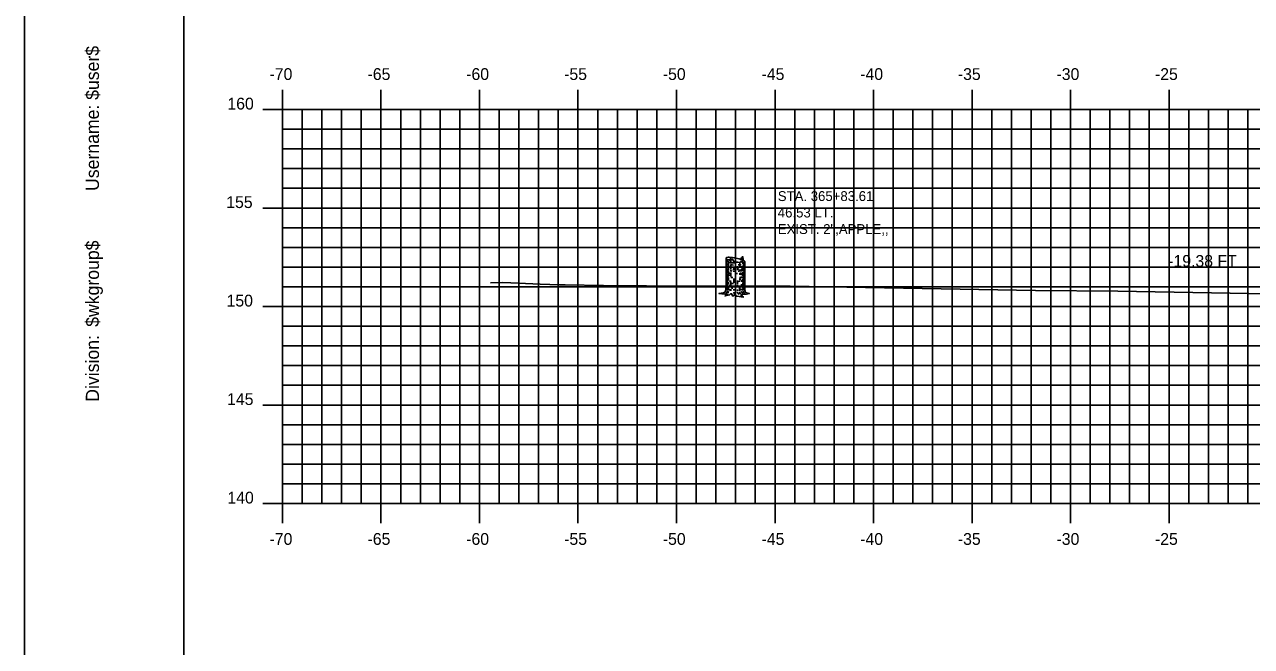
# Model space of a CAD drawing. Extents: x 1147412 to 1147582, y 608981 to 609091.
# Drawn here: x 1147411.6 to 1147473.9, y 609013.1 to 609044.6 of the extents above; entities that cross this region are included whole.
import ezdxf

# ---------------------------------------------------------------- set-up
doc = ezdxf.new("R2010")
doc.units = 0
for name, color, linetype in [('BORDER', 7, 'Continuous'), ('D_Text_Monospaced', 7, 'Continuous'), ('D_Text_Standard', 7, 'Continuous'), ('H_V ANNOTATION', 7, 'Continuous'), ('MAJOR', 7, 'Continuous'), ('MINOR', 7, 'Continuous'), ('PLOT BOUNDARY', 7, 'Continuous'), ('S_Roadway_Centerline', 7, 'Continuous'), ('S_Trees_Decid_NonPay', 7, 'Continuous')]:
    doc.layers.add(name, color=color, linetype=linetype)

msp = doc.modelspace()

# ---------------------------------------------------------------- linework, layer by layer
at = {"layer": 'BORDER'}
msp.add_lwpolyline([(1147419.698, 608984.335), (1147579.698, 608984.335), (1147579.698, 609089.335), (1147419.698, 609089.335)], close=True, dxfattribs=at)
at = {"layer": 'MAJOR'}
for p, q in [((1147424.697, 609041.337), (1147424.697, 609040.335)), ((1147429.697, 609041.337), (1147429.697, 609040.335)), ((1147434.697, 609041.337), (1147434.697, 609040.335)), ((1147439.697, 609041.337), (1147439.697, 609040.335)), ((1147444.697, 609041.337), (1147444.697, 609040.335)), ((1147449.697, 609041.337), (1147449.697, 609040.335)), ((1147454.697, 609041.337), (1147454.697, 609040.335)), ((1147459.697, 609041.337), (1147459.697, 609040.335)), ((1147464.697, 609041.337), (1147464.697, 609040.335)), ((1147469.697, 609041.337), (1147469.697, 609040.335)), ((1147423.695, 609040.335), (1147424.697, 609040.335)), ((1147424.697, 609040.335), (1147564.697, 609040.335)), ((1147424.697, 609020.335), (1147424.697, 609040.335)), ((1147424.697, 609020.335), (1147424.697, 609040.335)), ((1147424.697, 609040.335), (1147564.697, 609040.335)), ((1147429.697, 609020.335), (1147429.697, 609040.335)), ((1147434.697, 609020.335), (1147434.697, 609040.335)), ((1147439.697, 609020.335), (1147439.697, 609040.335)), ((1147444.697, 609020.335), (1147444.697, 609040.335)), ((1147449.697, 609020.335), (1147449.697, 609040.335)), ((1147454.697, 609020.335), (1147454.697, 609040.335)), ((1147459.697, 609020.335), (1147459.697, 609040.335)), ((1147464.697, 609020.335), (1147464.697, 609040.335)), ((1147469.697, 609020.335), (1147469.697, 609040.335)), ((1147423.695, 609035.335), (1147424.697, 609035.335)), ((1147424.697, 609035.335), (1147564.697, 609035.335)), ((1147423.695, 609030.335), (1147424.697, 609030.335)), ((1147424.697, 609030.335), (1147564.697, 609030.335)), ((1147423.695, 609025.335), (1147424.697, 609025.335)), ((1147424.697, 609025.335), (1147564.697, 609025.335)), ((1147423.695, 609020.335), (1147424.697, 609020.335)), ((1147424.697, 609020.335), (1147564.697, 609020.335)), ((1147424.697, 609020.335), (1147564.697, 609020.335)), ((1147424.697, 609019.333), (1147424.697, 609020.335)), ((1147429.697, 609019.333), (1147429.697, 609020.335)), ((1147434.697, 609019.333), (1147434.697, 609020.335)), ((1147439.697, 609019.333), (1147439.697, 609020.335)), ((1147444.697, 609019.333), (1147444.697, 609020.335)), ((1147449.697, 609019.333), (1147449.697, 609020.335)), ((1147454.697, 609019.333), (1147454.697, 609020.335)), ((1147459.697, 609019.333), (1147459.697, 609020.335)), ((1147464.697, 609019.333), (1147464.697, 609020.335)), ((1147469.697, 609019.333), (1147469.697, 609020.335))]:
    msp.add_line(p, q, dxfattribs=at)
at = {"layer": 'MINOR'}
for p, q in [((1147425.697, 609020.335), (1147425.697, 609040.335)), ((1147426.697, 609020.335), (1147426.697, 609040.335)), ((1147427.697, 609020.335), (1147427.697, 609040.335)), ((1147428.697, 609020.335), (1147428.697, 609040.335)), ((1147430.697, 609020.335), (1147430.697, 609040.335)), ((1147431.697, 609020.335), (1147431.697, 609040.335)), ((1147432.697, 609020.335), (1147432.697, 609040.335)), ((1147433.697, 609020.335), (1147433.697, 609040.335)), ((1147435.697, 609020.335), (1147435.697, 609040.335)), ((1147436.697, 609020.335), (1147436.697, 609040.335)), ((1147437.697, 609020.335), (1147437.697, 609040.335)), ((1147438.697, 609020.335), (1147438.697, 609040.335)), ((1147440.697, 609020.335), (1147440.697, 609040.335)), ((1147441.697, 609020.335), (1147441.697, 609040.335)), ((1147442.697, 609020.335), (1147442.697, 609040.335)), ((1147443.697, 609020.335), (1147443.697, 609040.335)), ((1147445.697, 609020.335), (1147445.697, 609040.335)), ((1147446.697, 609020.335), (1147446.697, 609040.335)), ((1147447.697, 609020.335), (1147447.697, 609040.335)), ((1147448.697, 609020.335), (1147448.697, 609040.335)), ((1147450.697, 609020.335), (1147450.697, 609040.335)), ((1147451.697, 609020.335), (1147451.697, 609040.335)), ((1147452.697, 609020.335), (1147452.697, 609040.335)), ((1147453.697, 609020.335), (1147453.697, 609040.335)), ((1147455.697, 609020.335), (1147455.697, 609040.335)), ((1147456.697, 609020.335), (1147456.697, 609040.335)), ((1147457.697, 609020.335), (1147457.697, 609040.335)), ((1147458.697, 609020.335), (1147458.697, 609040.335)), ((1147460.697, 609020.335), (1147460.697, 609040.335)), ((1147461.697, 609020.335), (1147461.697, 609040.335)), ((1147462.697, 609020.335), (1147462.697, 609040.335)), ((1147463.697, 609020.335), (1147463.697, 609040.335)), ((1147465.697, 609020.335), (1147465.697, 609040.335)), ((1147466.697, 609020.335), (1147466.697, 609040.335)), ((1147467.697, 609020.335), (1147467.697, 609040.335)), ((1147468.697, 609020.335), (1147468.697, 609040.335)), ((1147470.697, 609020.335), (1147470.697, 609040.335)), ((1147471.697, 609020.335), (1147471.697, 609040.335)), ((1147472.697, 609020.335), (1147472.697, 609040.335)), ((1147473.697, 609020.335), (1147473.697, 609040.335)), ((1147424.697, 609039.335), (1147564.697, 609039.335)), ((1147424.697, 609039.335), (1147425.699, 609039.335)), ((1147424.697, 609038.335), (1147564.697, 609038.335)), ((1147424.697, 609038.335), (1147425.699, 609038.335)), ((1147424.697, 609037.335), (1147564.697, 609037.335)), ((1147424.697, 609037.335), (1147425.699, 609037.335)), ((1147424.697, 609036.335), (1147564.697, 609036.335)), ((1147424.697, 609036.335), (1147425.699, 609036.335)), ((1147424.697, 609034.335), (1147564.697, 609034.335)), ((1147424.697, 609034.335), (1147425.699, 609034.335)), ((1147424.697, 609033.335), (1147564.697, 609033.335)), ((1147424.697, 609033.335), (1147425.699, 609033.335)), ((1147424.697, 609032.335), (1147564.697, 609032.335)), ((1147424.697, 609032.335), (1147425.699, 609032.335)), ((1147424.697, 609031.335), (1147564.697, 609031.335)), ((1147424.697, 609031.335), (1147425.699, 609031.335)), ((1147424.697, 609029.335), (1147564.697, 609029.335)), ((1147424.697, 609029.335), (1147425.699, 609029.335)), ((1147424.697, 609028.335), (1147564.697, 609028.335)), ((1147424.697, 609028.335), (1147425.699, 609028.335)), ((1147424.697, 609027.335), (1147564.697, 609027.335)), ((1147424.697, 609027.335), (1147425.699, 609027.335)), ((1147424.697, 609026.335), (1147564.697, 609026.335)), ((1147424.697, 609026.335), (1147425.699, 609026.335)), ((1147424.697, 609024.335), (1147564.697, 609024.335)), ((1147424.697, 609024.335), (1147425.699, 609024.335)), ((1147424.697, 609023.335), (1147564.697, 609023.335)), ((1147424.697, 609023.335), (1147425.699, 609023.335)), ((1147424.697, 609022.335), (1147564.697, 609022.335)), ((1147424.697, 609022.335), (1147425.699, 609022.335)), ((1147424.697, 609021.335), (1147564.697, 609021.335)), ((1147424.697, 609021.335), (1147425.699, 609021.335))]:
    msp.add_line(p, q, dxfattribs=at)
at = {"layer": 'PLOT BOUNDARY'}
msp.add_lwpolyline([(1147411.604, 608981.276), (1147581.604, 608981.276), (1147581.604, 609091.276), (1147411.604, 609091.276)], close=True, dxfattribs=at)
at = {"layer": 'S_Roadway_Centerline'}
msp.add_lwpolyline([(1147435.257, 609031.545), (1147435.842, 609031.546), (1147436.283, 609031.53), (1147437.773, 609031.477), (1147438.759, 609031.444), (1147439.053, 609031.435), (1147440.99, 609031.398), (1147443.169, 609031.384), (1147450.474, 609031.373), (1147462.918, 609031.149), (1147467.093, 609031.118), (1147476.613, 609030.948)], dxfattribs=at)
at = {"layer": 'S_Trees_Decid_NonPay'}
for p, q in [((1147447.272, 609032.74), (1147447.272, 609032.645)), ((1147447.272, 609032.419), (1147447.272, 609032.336)), ((1147447.272, 609032.267), (1147447.272, 609032.015)), ((1147447.341, 609032.653), (1147447.341, 609032.353)), ((1147447.341, 609032.324), (1147447.341, 609032.192)), ((1147447.341, 609032.158), (1147447.341, 609031.878)), ((1147447.459, 609032.67), (1147447.459, 609032.522)), ((1147447.459, 609032.474), (1147447.459, 609032.305)), ((1147447.606, 609032.624), (1147447.606, 609032.517)), ((1147447.606, 609032.289), (1147447.606, 609032.202)), ((1147447.606, 609032.168), (1147447.606, 609032.097)), ((1147447.786, 609032.388), (1147447.786, 609032.188)), ((1147447.904, 609032.572), (1147447.904, 609032.493)), ((1147447.904, 609032.406), (1147447.904, 609032.322)), ((1147447.904, 609032.211), (1147447.904, 609032.11)), ((1147447.99, 609032.388), (1147447.99, 609032.301)), ((1147447.99, 609032.231), (1147447.99, 609032.11)), ((1147448.061, 609032.561), (1147448.061, 609032.509)), ((1147448.061, 609032.406), (1147448.061, 609032.324)), ((1147448.061, 609032.289), (1147448.061, 609032.215)), ((1147448.061, 609032.188), (1147448.061, 609032.128)), ((1147448.104, 609032.566), (1147448.104, 609032.349)), ((1147448.104, 609032.28), (1147448.104, 609032.128)), ((1147448.131, 609032.496), (1147448.131, 609032.414)), ((1147448.131, 609032.345), (1147448.131, 609032.215)), ((1147448.131, 609032.192), (1147448.131, 609032.011)), ((1147447.272, 609031.933), (1147447.272, 609031.702)), ((1147447.272, 609031.632), (1147447.272, 609031.471)), ((1147447.341, 609031.807), (1147447.341, 609031.663)), ((1147447.341, 609031.593), (1147447.341, 609031.451)), ((1147447.459, 609031.999), (1147447.459, 609031.851)), ((1147447.459, 609031.581), (1147447.459, 609031.428)), ((1147447.606, 609031.764), (1147447.606, 609031.542)), ((1147447.786, 609031.65), (1147447.786, 609031.463)), ((1147447.904, 609032.025), (1147447.904, 609031.949)), ((1147447.904, 609031.764), (1147447.904, 609031.667)), ((1147447.99, 609032.034), (1147447.99, 609031.92)), ((1147447.99, 609031.858), (1147447.99, 609031.776)), ((1147447.99, 609031.69), (1147447.99, 609031.593)), ((1147448.061, 609032.075), (1147448.061, 609031.894)), ((1147448.061, 609031.862), (1147448.061, 609031.78)), ((1147448.061, 609031.727), (1147448.061, 609031.556)), ((1147448.061, 609031.523), (1147448.061, 609031.243)), ((1147448.104, 609032.023), (1147448.104, 609031.945)), ((1147448.104, 609031.918), (1147448.104, 609031.811)), ((1147448.104, 609031.776), (1147448.104, 609031.675)), ((1147448.104, 609031.65), (1147448.104, 609031.467)), ((1147448.131, 609031.963), (1147448.131, 609031.717)), ((1147448.131, 609031.698), (1147448.131, 609031.603)), ((1147448.133, 609031.55), (1147448.131, 609031.29)), ((1147447.272, 609031.455), (1147447.272, 609031.35)), ((1147447.272, 609031.313), (1147447.272, 609031.189)), ((1147447.34, 609031.109), (1147447.299, 609031.013)), ((1147447.341, 609031.35), (1147447.341, 609031.169)), ((1147447.459, 609031.216), (1147447.459, 609031.138)), ((1147447.606, 609031.208), (1147447.606, 609031.142)), ((1147447.646, 609030.922), (1147447.612, 609031.068)), ((1147447.786, 609031.433), (1147447.786, 609031.379)), ((1147447.786, 609031.204), (1147447.786, 609031.113)), ((1147447.904, 609031.342), (1147447.904, 609031.118)), ((1147447.99, 609031.463), (1147447.99, 609031.364)), ((1147447.99, 609031.235), (1147447.99, 609031.177)), ((1147448.061, 609031.191), (1147448.061, 609031.165)), ((1147448.102, 609031.126), (1147448.137, 609031.074)), ((1147448.104, 609031.364), (1147448.104, 609031.173)), ((1147448.184, 609031.004), (1147448.116, 609031.035)), ((1147448.131, 609031.252), (1147448.131, 609031.177))]:
    msp.add_line(p, q, dxfattribs=at)
for points in [[(1147448.172, 609032.604), (1147448.172, 609031.192), (1147448.194, 609031.044), (1147448.398, 609031), (1147448.258, 609030.965), (1147448.04, 609030.946), (1147447.97, 609030.903), (1147448.091, 609030.815), (1147447.76, 609030.858), (1147447.646, 609030.922), (1147447.554, 609030.862), (1147447.498, 609030.941), (1147447.507, 609030.977), (1147447.445, 609030.979), (1147447.393, 609030.922), (1147447.161, 609030.87), (1147447.288, 609030.959), (1147447.156, 609030.961), (1147446.848, 609030.998), (1147447.087, 609031.029), (1147447.165, 609031.087), (1147447.204, 609031.208), (1147447.221, 609031.562), (1147447.221, 609032.795)], [(1147447.585, 609032.629), (1147447.576, 609032.696), (1147447.552, 609032.701), (1147447.543, 609032.736), (1147447.513, 609032.721), (1147447.498, 609032.736), (1147447.474, 609032.713), (1147447.451, 609032.721), (1147447.438, 609032.771), (1147447.431, 609032.727), (1147447.4, 609032.736), (1147447.396, 609032.685)], [(1147448.077, 609032.685), (1147448.073, 609032.779), (1147448.059, 609032.752), (1147448.059, 609032.874), (1147448.038, 609032.81), (1147448.023, 609032.843), (1147448.007, 609032.787), (1147447.99, 609032.804), (1147447.972, 609032.795), (1147447.953, 609032.729)], [(1147448.055, 609032.561), (1147448.038, 609032.622), (1147448.015, 609032.61), (1147447.984, 609032.645), (1147447.951, 609032.567)], [(1147447.27, 609031.147), (1147447.261, 609031.07), (1147447.183, 609031.021)], [(1147447.795, 609031.064), (1147447.795, 609031.027), (1147447.846, 609030.996), (1147447.863, 609030.946)], [(1147447.906, 609031.07), (1147447.912, 609031), (1147447.976, 609030.988)], [(1147448.054, 609031.035), (1147448.011, 609031.07), (1147448.003, 609031.118)], [(1147448.133, 609031.051), (1147448.054, 609031.035), (1147448.038, 609030.992)]]:
    msp.add_lwpolyline(points, dxfattribs=at)
for centre, radius, start, end in [((1147447.239, 609032.796), 0.0179, 152.11676, 168.17229), ((1147447.239, 609032.796), 0.0179, 168.17229, 184.22782), ((1147447.245, 609032.796), 0.0237, 184.22782, 198.17229), ((1147447.254, 609032.799), 0.0336, 198.17229, 216.94859), ((1147447.244, 609032.793), 0.0237, 138.17229, 152.11676), ((1147447.251, 609032.786), 0.0336, 119.39599, 138.17229), ((1147447.302, 609032.835), 0.0935, 216.9486, 228.17229), ((1147447.281, 609032.734), 0.0935, 108.17229, 119.39599), ((1147447.454, 609033.005), 0.322, 228.17229, 250.29024), ((1147447.352, 609032.517), 0.322, 86.05435, 108.17229), ((1147447.202, 609030.337), 2.507, 78.17229, 86.05435), ((1147447.202, 609030.337), 2.507, 70.29024, 78.17229), ((1147447.239, 609032.648), 0.0191, 163.94846, 180), ((1147447.239, 609032.648), 0.0191, 180, 196.05154), ((1147447.239, 609032.434), 0.0191, 163.94846, 180), ((1147447.239, 609032.434), 0.0191, 180, 196.05154), ((1147447.239, 609032.331), 0.0191, 163.94846, 180), ((1147447.239, 609032.331), 0.0191, 180, 196.05154), ((1147447.239, 609032.111), 0.0191, 163.94846, 180), ((1147447.239, 609032.111), 0.0191, 180, 196.05154), ((1147447.245, 609032.65), 0.0252, 196.05154, 210), ((1147447.245, 609032.436), 0.0252, 196.05154, 210), ((1147447.245, 609032.333), 0.0252, 196.05154, 210), ((1147447.245, 609032.113), 0.0252, 196.05154, 210), ((1147447.254, 609032.655), 0.0356, 210, 228.74941), ((1147447.254, 609032.441), 0.0356, 210, 228.74941), ((1147447.254, 609032.338), 0.0356, 210, 228.74941), ((1147447.296, 609032.702), 0.0984, 228.74941, 240), ((1147447.296, 609032.488), 0.0984, 228.74941, 240), ((1147447.296, 609032.385), 0.0984, 228.74941, 240), ((1147447.409, 609032.899), 0.326, 240, 248.32432), ((1147447.409, 609032.685), 0.326, 240, 243.57187), ((1147447.409, 609032.582), 0.326, 240, 243.24303), ((1147447.409, 609032.786), 0.326, 240.90989, 257.8036), ((1147447.409, 609032.477), 0.326, 245.15448, 257.8036), ((1147447.409, 609032.685), 0.326, 250.41675, 261.8968), ((1147447.409, 609032.582), 0.326, 251.68306, 257.8036), ((1147447.409, 609032.899), 0.326, 257.8036, 261.8968), ((1147448.191, 609035.062), 2.507, 250.29024, 251.52809), ((1147447.696, 609034.909), 2.356, 261.8968, 263.27991), ((1147447.696, 609034.695), 2.356, 261.8968, 262.55191), ((1147447.696, 609034.487), 2.356, 263.26817, 265.63617), ((1147447.696, 609034.592), 2.356, 263.34129, 264.99462), ((1147447.696, 609034.796), 2.356, 264.24201, 267.36728), ((1147447.696, 609034.909), 2.356, 265.24001, 267.83857), ((1147447.696, 609034.592), 2.356, 266.50356, 267.83857), ((1147448.191, 609035.062), 2.507, 255.99867, 258.17229), ((1147448.191, 609035.062), 2.507, 258.17229, 264.50134), ((1147447.696, 609034.695), 2.356, 270.81188, 272.1981), ((1147447.696, 609034.592), 2.356, 272.1981, 273.97408), ((1147447.696, 609034.487), 2.356, 273.0067, 275.06467), ((1147447.696, 609034.796), 2.356, 273.14807, 276.77338), ((1147447.696, 609034.695), 2.356, 275.06468, 278.1032), ((1147447.696, 609034.487), 2.356, 277.18685, 278.1032), ((1147447.696, 609034.592), 2.356, 277.38384, 278.1032), ((1147447.982, 609032.685), 0.326, 278.1032, 279.08543), ((1147447.982, 609032.582), 0.326, 278.1032, 284.03823), ((1147447.982, 609032.477), 0.326, 278.1032, 284.03823), ((1147447.939, 609032.394), 0.322, 48.17229, 70.29024), ((1147448.041, 609032.882), 0.322, 272.44787, 288.17229), ((1147447.982, 609032.786), 0.326, 291.95057, 300), ((1147447.982, 609032.685), 0.326, 291.95057, 300), ((1147447.982, 609032.477), 0.326, 291.95057, 300), ((1147448.112, 609032.665), 0.0935, 288.17229, 299.39599), ((1147448.096, 609032.589), 0.0984, 300, 311.25059), ((1147448.096, 609032.488), 0.0984, 300, 311.25059), ((1147448.096, 609032.28), 0.0984, 300, 311.25059), ((1147448.091, 609032.564), 0.0935, 36.9486, 48.17229), ((1147448.141, 609032.613), 0.0336, 299.39599, 318.17229), ((1147448.137, 609032.542), 0.0356, 311.25059, 330), ((1147448.137, 609032.441), 0.0356, 311.25059, 330), ((1147448.137, 609032.233), 0.0356, 311.25059, 330), ((1147448.139, 609032.6), 0.0336, 18.17229, 36.94859), ((1147448.149, 609032.607), 0.0237, 318.17229, 332.11676), ((1147448.146, 609032.537), 0.0252, 330, 343.94846), ((1147448.146, 609032.436), 0.0252, 330, 343.94846), ((1147448.146, 609032.228), 0.0252, 330, 343.94846), ((1147448.146, 609032.113), 0.0252, 330, 343.94846), ((1147448.154, 609032.604), 0.0179, 332.11676, 348.17229), ((1147448.152, 609032.535), 0.0191, 343.94846, 360), ((1147448.152, 609032.434), 0.0191, 343.94846, 360), ((1147448.152, 609032.331), 0.0191, 343.94846, 360), ((1147448.152, 609032.226), 0.0191, 343.94846, 360), ((1147448.152, 609032.111), 0.0191, 343.94846, 360), ((1147448.148, 609032.604), 0.0237, 4.22782, 18.17229), ((1147448.154, 609032.604), 0.0179, 348.17229, 4.22783), ((1147448.152, 609032.535), 0.0191, 360, 6.11276), ((1147448.152, 609032.434), 0.0191, 360, 6.11276), ((1147448.152, 609032.331), 0.0191, 360, 6.11276), ((1147448.152, 609032.226), 0.0191, 360, 6.11276), ((1147448.152, 609032.111), 0.0191, 360, 6.11276), ((1147447.237, 609031.896), 0.0191, 163.94846, 180), ((1147447.239, 609031.792), 0.0191, 163.94846, 180), ((1147447.239, 609031.792), 0.0191, 180, 196.05154), ((1147447.24, 609031.997), 0.0191, 163.94846, 180), ((1147447.24, 609031.997), 0.0191, 180, 196.05154), ((1147447.245, 609031.793), 0.0252, 196.05154, 210), ((1147447.246, 609031.998), 0.0252, 196.05154, 210), ((1147447.254, 609032.118), 0.0356, 210, 228.74941), ((1147447.254, 609031.799), 0.0356, 210, 228.74941), ((1147447.255, 609032.004), 0.0356, 210, 228.74941), ((1147447.296, 609032.165), 0.0984, 228.74941, 240), ((1147447.296, 609032.051), 0.0984, 228.74941, 240), ((1147447.296, 609031.846), 0.0984, 228.74941, 240), ((1147447.407, 609032.148), 0.326, 240, 256.90786), ((1147447.409, 609032.362), 0.326, 240, 245.15448), ((1147447.409, 609032.043), 0.326, 240, 245.15448), ((1147447.41, 609032.248), 0.326, 240, 247.86558), ((1147447.409, 609031.952), 0.326, 241.93896, 253.9183), ((1147447.41, 609032.248), 0.326, 257.66994, 261.8968), ((1147447.696, 609034.258), 2.356, 261.8968, 262.86151), ((1147447.696, 609033.962), 2.356, 262.58433, 264.48651), ((1147447.696, 609034.372), 2.356, 262.65877, 264.79114), ((1147447.696, 609033.849), 2.356, 264.24201, 267.46903), ((1147447.693, 609034.158), 2.356, 264.3443, 266.85288), ((1147447.696, 609034.053), 2.356, 267.83857, 269.00542), ((1147447.696, 609034.372), 2.356, 269.55779, 270), ((1147447.696, 609034.372), 2.356, 270, 272.414), ((1147447.696, 609033.962), 2.356, 272.1981, 275.27259), ((1147447.693, 609034.158), 2.356, 274.97344, 277.24554), ((1147447.696, 609034.372), 2.356, 275.06467, 277.18685), ((1147447.696, 609034.053), 2.356, 275.06467, 276.42799), ((1147447.982, 609032.362), 0.326, 284.03823, 300), ((1147447.983, 609032.248), 0.326, 283.90364, 291.80982), ((1147447.982, 609032.043), 0.326, 284.03823, 291.95057), ((1147447.982, 609031.839), 0.326, 284.03823, 291.95057), ((1147447.979, 609032.148), 0.326, 292.40493, 300), ((1147447.983, 609032.248), 0.326, 297.00583, 300), ((1147447.982, 609032.043), 0.326, 297.15252, 300), ((1147448.093, 609031.95), 0.0984, 300, 311.25059), ((1147448.096, 609032.165), 0.0984, 300, 311.25059), ((1147448.096, 609031.846), 0.0984, 300, 311.25059), ((1147448.096, 609032.051), 0.0984, 300, 311.25059), ((1147448.135, 609031.903), 0.0356, 311.25059, 330), ((1147448.137, 609032.118), 0.0356, 311.25059, 330), ((1147448.138, 609032.004), 0.0356, 311.25059, 330), ((1147448.137, 609031.799), 0.0356, 311.25059, 330), ((1147448.144, 609031.898), 0.0252, 330, 343.94846), ((1147448.15, 609031.896), 0.0191, 343.94846, 360), ((1147448.146, 609031.793), 0.0252, 330, 343.94846), ((1147448.147, 609031.998), 0.0252, 330, 343.94846), ((1147448.15, 609031.896), 0.0191, 0, 6.11277), ((1147448.152, 609031.792), 0.0191, 343.94846, 360), ((1147448.153, 609031.997), 0.0191, 343.94846, 360), ((1147448.152, 609031.792), 0.0191, 360, 6.11276), ((1147448.152, 609031.701), 0.0191, 360, 6.11276), ((1147448.153, 609031.997), 0.0191, 0, 6.11277), ((1147447.225, 609031.252), 0.0191, 163.94846, 180), ((1147447.225, 609031.252), 0.0191, 180, 196.05154), ((1147447.231, 609031.253), 0.0252, 196.05154, 210), ((1147447.24, 609031.259), 0.0356, 210, 228.74941), ((1147447.23, 609031.362), 0.0191, 163.94846, 180), ((1147447.23, 609031.362), 0.0191, 180, 196.05154), ((1147447.236, 609031.364), 0.0252, 196.05154, 210), ((1147447.245, 609031.369), 0.0356, 210, 228.74941), ((1147447.235, 609031.473), 0.0191, 163.94846, 180), ((1147447.235, 609031.473), 0.0191, 180, 196.05154), ((1147447.281, 609031.306), 0.0984, 228.74941, 240), ((1147447.241, 609031.474), 0.0252, 196.05154, 210), ((1147447.25, 609031.479), 0.0356, 210, 228.74941), ((1147447.287, 609031.416), 0.0984, 228.74941, 240), ((1147447.291, 609031.527), 0.0984, 228.74941, 240), ((1147447.395, 609031.503), 0.326, 240, 247.9161), ((1147447.4, 609031.613), 0.326, 240, 241.90969), ((1147447.405, 609031.724), 0.326, 240, 245.93749), ((1147447.395, 609031.503), 0.326, 260.38342, 261.8968), ((1147447.681, 609033.513), 2.356, 261.8968, 263.53328), ((1147447.692, 609033.734), 2.356, 262.22258, 264.4852), ((1147447.687, 609033.623), 2.356, 264.90887, 266.81578), ((1147447.687, 609033.623), 2.356, 274.18643, 275.28293), ((1147447.681, 609033.513), 2.356, 274.55512, 275.4167), ((1147447.692, 609033.734), 2.356, 277.28629, 278.1032), ((1147447.681, 609033.513), 2.356, 277.54032, 278.1032), ((1147447.967, 609031.503), 0.326, 278.1032, 294.70938), ((1147447.978, 609031.724), 0.326, 278.1032, 284.77414), ((1147447.973, 609031.613), 0.326, 293.6544, 300), ((1147448.081, 609031.306), 0.0984, 300, 311.25059), ((1147448.092, 609031.527), 0.0984, 300, 311.25059), ((1147448.123, 609031.259), 0.0356, 311.25059, 330), ((1147448.132, 609031.253), 0.0252, 330, 343.94846), ((1147448.133, 609031.479), 0.0356, 311.25059, 330), ((1147448.138, 609031.252), 0.0191, 0, 6.11277), ((1147448.138, 609031.252), 0.0191, 343.94846, 360), ((1147448.142, 609031.474), 0.0252, 330, 343.94846), ((1147448.148, 609031.473), 0.0191, 343.94846, 360), ((1147448.148, 609031.473), 0.0191, 360, 6.11276)]:
    msp.add_arc(centre, radius, start, end, dxfattribs=at)

# ---------------------------------------------------------------- texts
at = {"layer": 'BORDER'}
for s, p in [('$user$', (1147415.383, 609040.827)), ('Username:', (1147415.383, 609036.203)), ('$wkgroup$', (1147415.383, 609029.305)), ('Division:', (1147415.383, 609025.501))]:
    msp.add_text(s, height=0.6696, rotation=90, dxfattribs=at).set_placement(p)
at = {"layer": 'D_Text_Monospaced'}
for s, height, p in [('STA. 365+83.61', 0.49998, (1147449.839, 609035.69)), ('46.53 LT.', 0.5, (1147449.839, 609034.856)), ('EXIST. 2",APPLE,,', 0.49998, (1147449.839, 609034.016))]:
    msp.add_text(s, height=height, dxfattribs=at).set_placement(p)
at = {"layer": 'D_Text_Standard'}
msp.add_text('-19.38 FT', height=0.6, dxfattribs=at).set_placement((1147469.656, 609032.348))
at = {"layer": 'H_V ANNOTATION'}
for s, p in [('-70', (1147424.039, 609041.835)), ('-65', (1147429.015, 609041.835)), ('-60', (1147434.023, 609041.835)), ('-55', (1147438.994, 609041.835)), ('-50', (1147444.002, 609041.835)), ('-45', (1147449.015, 609041.835)), ('-40', (1147454.023, 609041.835)), ('-35', (1147458.978, 609041.835)), ('-30', (1147463.986, 609041.835)), ('-25', (1147468.983, 609041.835)), ('160', (1147421.902, 609040.335)), ('155', (1147421.843, 609035.335)), ('150', (1147421.859, 609030.335)), ('145', (1147421.886, 609025.335)), ('140', (1147421.902, 609020.335)), ('-70', (1147424.039, 609018.235)), ('-65', (1147429.015, 609018.235)), ('-60', (1147434.023, 609018.235)), ('-55', (1147438.994, 609018.235)), ('-50', (1147444.002, 609018.235)), ('-45', (1147449.015, 609018.235)), ('-40', (1147454.023, 609018.235)), ('-35', (1147458.978, 609018.235)), ('-30', (1147463.986, 609018.235)), ('-25', (1147468.983, 609018.235))]:
    msp.add_text(s, height=0.6, dxfattribs=at).set_placement(p)
at = {"layer": 'MAJOR'}
msp.add_text('-', height=0.006, dxfattribs=at).set_placement((1147424.693, 609020.335))

doc.saveas('drawing.dxf')
